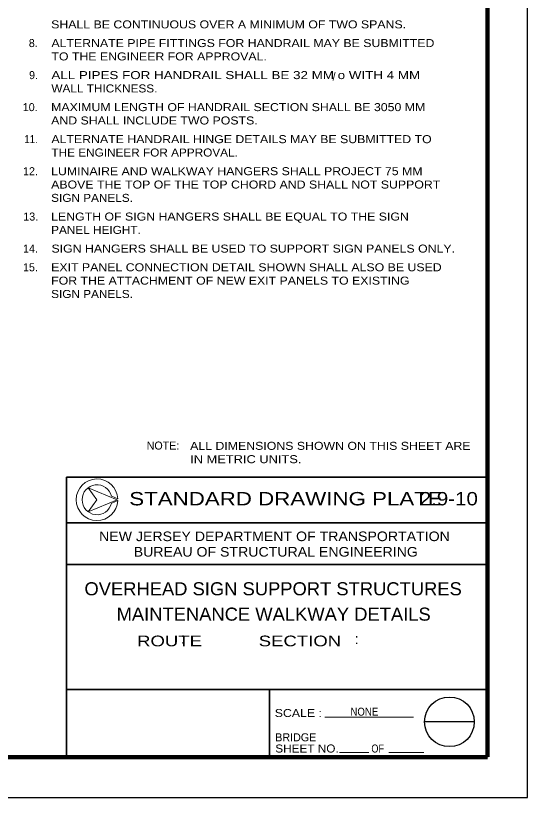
# Model space of a CAD drawing. Extents: x 312601.858 to 312602.699, y 144420.109 to 144420.704.
# Drawn here: x 312602.507 to 312602.6988, y 144420.1095 to 144420.4024 of the extents above; entities that cross this region are included whole.
import ezdxf
from ezdxf.enums import TextEntityAlignment as Align

# ---------------------------------------------------------------- set-up
doc = ezdxf.new("R2010")
doc.units = 0
doc.header["$LTSCALE"] = 0.0012
for name, color, linetype, lineweight in [('1', 7, 'Continuous', 13), ('2', 7, 'Continuous', 13), ('39', 7, 'Continuous', 13), ('4', 7, 'Continuous', 13)]:
    doc.layers.add(name, color=color, linetype=linetype, lineweight=lineweight)

msp = doc.modelspace()

# ---------------------------------------------------------------- linework, layer by layer
at = {"layer": '1'}
msp.add_line((312602.543, 144420.2197), (312602.5453, 144420.2207), dxfattribs=at)
for points in [[(312602.5451, 144420.221), (312602.5342, 144420.2255), (312602.5451, 144420.221)], [(312602.5453, 144420.2213), (312602.543, 144420.2223), (312602.5429, 144420.2223)]]:
    msp.add_lwpolyline(points, dxfattribs=at)
for points in [[(312602.5451, 144420.221), (312602.5342, 144420.2255), (312602.5374, 144420.221), (312602.5342, 144420.2165)], [(312602.5374, 144420.221), (312602.5342, 144420.2165), (312602.5451, 144420.221), (312602.5342, 144420.2255)]]:
    msp.add_lwpolyline(points, close=True, dxfattribs=at)
for radius, start, end in [(0.007803, 2.21392, 357.78608), (0.0056, 13.69411, 346.30589)]:
    msp.add_arc((312602.5375, 144420.221), radius, start, end, dxfattribs=at)
at = {"layer": '39', "lineweight": 25}
for p, q in [((312602.6988, 144420.1095), (312602.6988, 144420.7035)), ((312602.6789, 144420.1378), (312602.6603, 144420.1378)), ((312602.452, 144420.1245), (312602.6838, 144420.1245)), ((312601.8578, 144420.1095), (312602.6988, 144420.1095))]:
    msp.add_line(p, q, dxfattribs=at)
at = {"layer": '39', "lineweight": 158}
for p, q in [((312602.6838, 144420.1247), (312602.6838, 144420.6645)), ((312601.9088, 144420.1245), (312602.6838, 144420.1245))]:
    msp.add_line(p, q, dxfattribs=at)
at = {"layer": '39', "lineweight": 35}
for p, q in [((312602.526, 144420.1245), (312602.526, 144420.2295)), ((312602.526, 144420.2295), (312602.6838, 144420.2295)), ((312602.6838, 144420.2297), (312602.6838, 144420.1247)), ((312602.6838, 144420.2297), (312602.6838, 144420.1247)), ((312602.6838, 144420.2295), (312602.6838, 144420.1245)), ((312602.526, 144420.2124), (312602.6838, 144420.2124)), ((312602.526, 144420.1968), (312602.6838, 144420.1968)), ((312602.526, 144420.1499), (312602.6838, 144420.1499)), ((312602.6022, 144420.1248), (312602.6022, 144420.1499))]:
    msp.add_line(p, q, dxfattribs=at)
at = {"layer": '39'}
for p, q in [((312602.6022, 144420.1499), (312602.6838, 144420.1499)), ((312602.6022, 144420.1248), (312602.6022, 144420.1499)), ((312602.6022, 144420.1248), (312602.6022, 144420.1499)), ((312602.6229, 144420.1395), (312602.6561, 144420.1395)), ((312602.6284, 144420.1263), (312602.6394, 144420.1263)), ((312602.6469, 144420.1263), (312602.66, 144420.1263))]:
    msp.add_line(p, q, dxfattribs=at)
msp.add_lwpolyline([(312602.5451, 144420.221), (312602.5342, 144420.2255), (312602.5374, 144420.221), (312602.5342, 144420.2165)], close=True, dxfattribs=at)
at = {"layer": '39', "lineweight": 25}
msp.add_circle((312602.6696, 144420.1378), 0.0093, dxfattribs=at)

# ---------------------------------------------------------------- texts
at = {"layer": '2'}
for s, width, p in [('SHALL BE CONTINUOUS OVER A MINIMUM OF TWO SPANS.', 1.15, (312602.5203, 144420.3976)), ('ALTERNATE PIPE FITTINGS FOR HANDRAIL MAY BE SUBMITTED', 1.15, (312602.5204, 144420.3906)), ('TO THE ENGINEER FOR APPROVAL.', 1.15, (312602.5204, 144420.3856)), ('ALL PIPES FOR HANDRAIL SHALL BE 32 MM o WITH 4 MM', 1.25, (312602.5204, 144420.3786)), ('WALL THICKNESS.', 1.1, (312602.5204, 144420.3736)), ('MAXIMUM LENGTH OF HANDRAIL SECTION SHALL BE 3050 MM', 1.15, (312602.5203, 144420.3666)), ('AND SHALL INCLUDE TWO POSTS.', 1.15, (312602.5203, 144420.3616)), ('ALTERNATE HANDRAIL HINGE DETAILS MAY BE SUBMITTED TO', 1.15, (312602.5204, 144420.3546)), ('THE ENGINEER FOR APPROVAL.', 1.1, (312602.5204, 144420.3496)), ('LUMINAIRE AND WALKWAY HANGERS SHALL PROJECT 75 MM', 1.15, (312602.5203, 144420.3426)), ('ABOVE THE TOP OF THE TOP CHORD AND SHALL NOT SUPPORT', 1.15, (312602.5203, 144420.3376)), ('SIGN PANELS.', 1.1, (312602.5203, 144420.3326)), ('LENGTH OF SIGN HANGERS SHALL BE EQUAL TO THE SIGN', 1.15, (312602.5203, 144420.3256)), ('PANEL HEIGHT.', 1.1, (312602.5203, 144420.3206)), ('EXIT PANEL CONNECTION DETAIL SHOWN SHALL ALSO BE USED', 1.15, (312602.5203, 144420.3066)), ('FOR THE ATTACHMENT OF NEW EXIT PANELS TO EXISTING', 1.15, (312602.5203, 144420.3016)), ('SIGN PANELS.', 1.1, (312602.5203, 144420.2966))]:
    msp.add_text(s, height=0.003, dxfattribs=dict(at, width=width)).set_placement(p)
for s, p in [('8.', (312602.5136, 144420.3906)), ('9.', (312602.5137, 144420.3786)), ('/', (312602.62635, 144420.3781)), ('10.', (312602.51245, 144420.3666)), ('12.', (312602.51255, 144420.3426)), ('13.', (312602.51265, 144420.3256)), ('14.', (312602.51255, 144420.3136)), ('15.', (312602.51255, 144420.3066))]:
    msp.add_text(s, height=0.003, dxfattribs=at).set_placement(p, align=Align.CENTER)
for s, height, width, p in [('11.', 0.003, 0.9, (312602.51275, 144420.3546)), ('SIGN HANGERS SHALL BE USED TO SUPPORT SIGN PANELS ONLY.', 0.003, 1.15, (312602.59605, 144420.3136)), ('2.9-10', 0.005, 1.15, (312602.66935, 144420.2189)), ('OVERHEAD SIGN SUPPORT STRUCTURES', 0.0049, 1.05, (312602.6035, 144420.1852)), ('MAINTENANCE WALKWAY DETAILS', 0.0049, 1.05, (312602.6037, 144420.1757)), ('NONE', 0.003, 0.9, (312602.6377, 144420.1401))]:
    msp.add_text(s, height=height, dxfattribs=dict(at, width=width)).set_placement(p, align=Align.CENTER)
at = {"layer": '39'}
for s, height, width, p in [('STANDARD DRAWING PLATE       ', 0.005, 1.25, (312602.61645, 144420.2189)), ('NEW JERSEY DEPARTMENT OF TRANSPORTATION', 0.003599, 1.1, (312602.604, 144420.2055)), ('BUREAU OF STRUCTURAL ENGINEERING', 0.0036, 1.1, (312602.6045, 144420.1997)), ('ROUTE           SECTION', 0.004, 1.3, (312602.59075, 144420.1661)), ('SCALE :', 0.003, 1.15, (312602.61295, 144420.1396)), ('OF', 0.003, 0.85, (312602.6427, 144420.1263))]:
    msp.add_text(s, height=height, dxfattribs=dict(at, width=width)).set_placement(p, align=Align.CENTER)
for p in [(312602.569737, 144420.1671), (312602.634837, 144420.1669)]:
    msp.add_text(':', height=0.004, dxfattribs=at).set_placement(p, align=Align.CENTER)
msp.add_text('BRIDGE', height=0.003, dxfattribs=at).set_placement((312602.6043, 144420.1305))
at = {"layer": '39', "width": 1.1}
msp.add_text('SHEET NO.', height=0.003, dxfattribs=at).set_placement((312602.6043, 144420.1263))
at = {"layer": '4'}
msp.add_text('NOTE:', height=0.003, dxfattribs=at).set_placement((312602.5561, 144420.2398))
for s, width, p in [('ALL DIMENSIONS SHOWN ON THIS SHEET ARE', 1.15, (312602.5724, 144420.2397)), ('IN METRIC UNITS.', 1.2, (312602.5724, 144420.2347))]:
    msp.add_text(s, height=0.003, dxfattribs=dict(at, width=width)).set_placement(p)

doc.saveas('drawing.dxf')
